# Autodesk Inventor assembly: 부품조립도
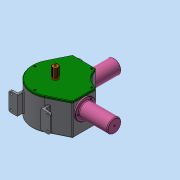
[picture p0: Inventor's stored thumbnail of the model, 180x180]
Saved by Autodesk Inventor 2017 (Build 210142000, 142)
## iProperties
Part Number: 부품조립도
Material: 일반
Document SubType Name: Assembly
Designer: MRC
Mass: 3748.67 g
Surface Area: 4101.75 cm^2
Volume: 1119.43 cm^3
Density: 3.34872 g/cm^3
Author: MRC
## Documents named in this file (13)
- C:\Users\MRC\Desktop\611109V1004\부품조립도.iam
- C:\Users\MRC\Desktop\611109V1004\본체.ipt
- C:\Users\MRC\Desktop\611109V1004\너트 M3.ipt
- C:\Users\MRC\Desktop\611109V1004\베어링 20 x 37 x 9.ipt
- C:\Users\MRC\Desktop\611109V1004\볼트 M3 x 12.ipt
- C:\Users\MRC\Desktop\611109V1004\실린더.ipt
- C:\Users\MRC\Desktop\611109V1004\앞커버.ipt
- C:\Users\MRC\Desktop\611109V1004\축.ipt
- C:\Users\MRC\Desktop\611109V1004\측정게이지.ipt
- C:\Users\MRC\Desktop\611109V1004\커넥팅로드 캡.ipt
- C:\Users\MRC\Desktop\611109V1004\커넥팅로드.ipt
- C:\Users\MRC\Desktop\611109V1004\피스톤 핀.ipt
- C:\Users\MRC\Desktop\611109V1004\피스톤.ipt
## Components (4 placed, 2 different names)
1. 피스톤 핀:1
2. 피스톤:1
3. 피스톤:2
4. 피스톤 핀:2
